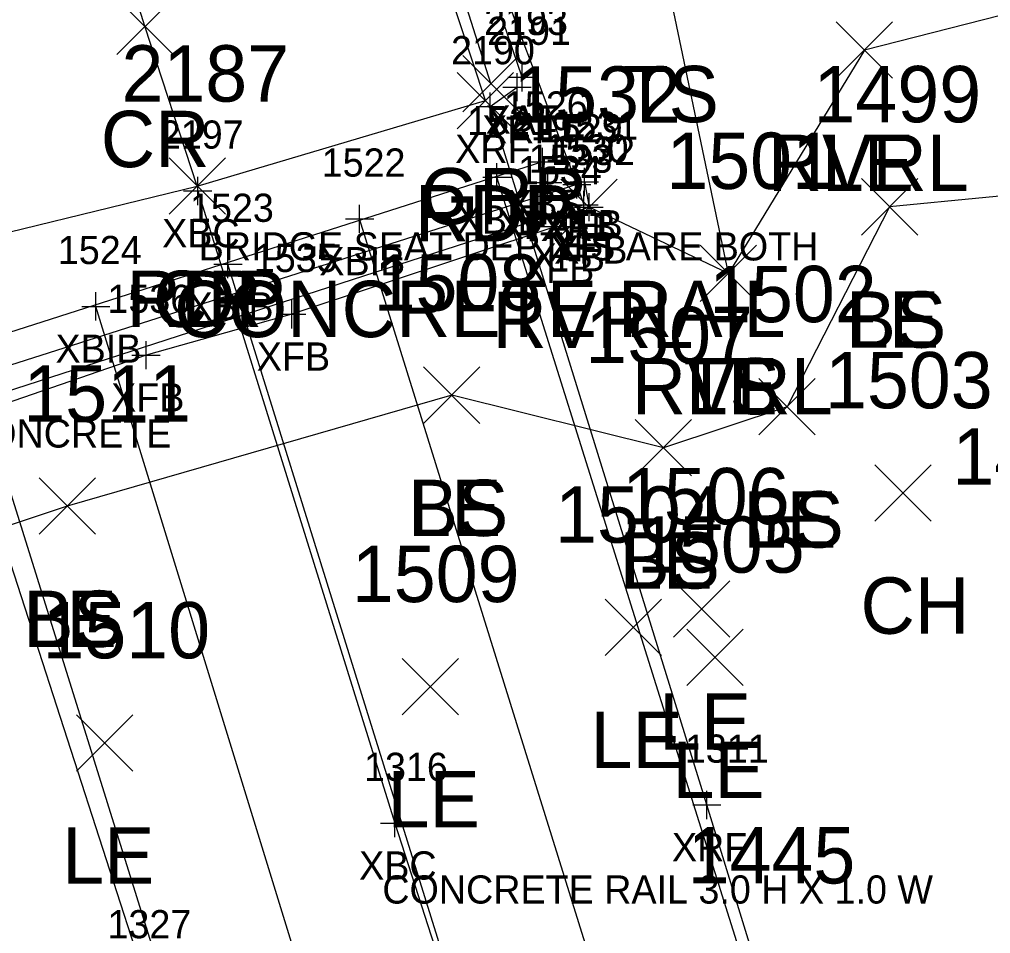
# Model space of a CAD drawing. Extents: x 1620157 to 1620595, y 115111 to 117885.
# Drawn here: x 1620323.63 to 1620358.1, y 115415.26 to 115447.7 of the extents above; entities that cross this region are included whole.
import ezdxf

# ---------------------------------------------------------------- set-up
doc = ezdxf.new("R2010")
doc.units = 0
for name, color, linetype in [('B_A', 7, 'Continuous'), ('B_C', 7, 'Continuous'), ('B_I', 7, 'Continuous'), ('B_TIC', 7, 'Continuous'), ('BB', 7, 'Continuous'), ('BELB', 7, 'Continuous'), ('BFT', 7, 'Continuous'), ('BR', 7, 'Continuous'), ('BSE', 7, 'Continuous'), ('BSUBM', 7, 'Continuous'), ('L_A', 7, 'Continuous'), ('L_I', 7, 'Continuous'), ('L_TIC', 7, 'Continuous'), ('LAWE', 7, 'Continuous'), ('LELB', 7, 'Continuous'), ('P_A', 7, 'Continuous'), ('P_I', 7, 'Continuous'), ('P_TIC', 7, 'Continuous'), ('PET', 7, 'Continuous'), ('PRC', 7, 'Continuous'), ('R_A', 7, 'Continuous'), ('R_C', 7, 'Continuous'), ('R_TIC', 7, 'Continuous'), ('RGR', 7, 'Continuous')]:
    doc.layers.add(name, color=color, linetype=linetype)

msp = doc.modelspace()

# ---------------------------------------------------------------- linework, layer by layer
at = {"layer": 'B_TIC'}
for p, q in [((1620341.474, 115445.647), (1620341.549, 115445.647)), ((1620341.297, 115445.297), (1620341.372, 115445.297)), ((1620340.342, 115444.608), (1620340.418, 115444.608)), ((1620342.201, 115442.646), (1620342.277, 115442.646)), ((1620340.583, 115442.1), (1620340.658, 115442.1)), ((1620342.383, 115441.912), (1620342.458, 115441.912)), ((1620343.419, 115441.84), (1620343.495, 115441.84)), ((1620343.419, 115441.84), (1620343.495, 115441.84)), ((1620343.686, 115441.931), (1620343.761, 115441.931)), ((1620329.963, 115441.614), (1620330.038, 115441.614)), ((1620343.669, 115441.12), (1620343.745, 115441.12)), ((1620343.854, 115441.035), (1620343.93, 115441.035)), ((1620343.054, 115440.758), (1620343.13, 115440.758)), ((1620335.708, 115440.621), (1620335.784, 115440.621)), ((1620342.677, 115440.348), (1620342.752, 115440.348)), ((1620331.035, 115439.016), (1620331.111, 115439.016)), ((1620326.343, 115437.517), (1620326.419, 115437.517)), ((1620333.3, 115437.236), (1620333.375, 115437.236)), ((1620328.129, 115435.785), (1620328.204, 115435.785)), ((1620348.034, 115419.821), (1620348.109, 115419.821)), ((1620348.034, 115419.821), (1620348.109, 115419.821)), ((1620336.954, 115419.174), (1620337.03, 115419.174))]:
    msp.add_line(p, q, dxfattribs=at)
for points in [[(1620341.47, 115445.147), (1620341.47, 115446.147)], [(1620341.294, 115444.797), (1620341.294, 115445.797)], [(1620340.97, 115445.647), (1620341.97, 115445.647)], [(1620340.339, 115444.108), (1620340.339, 115445.108)], [(1620340.793, 115445.297), (1620341.794, 115445.297)], [(1620339.839, 115444.608), (1620340.839, 115444.608)], [(1620342.198, 115442.146), (1620342.198, 115443.146)], [(1620340.579, 115441.6), (1620340.579, 115442.6)], [(1620341.698, 115442.646), (1620342.698, 115442.646)], [(1620342.38, 115441.412), (1620342.38, 115442.412)], [(1620343.682, 115441.431), (1620343.682, 115442.431)], [(1620329.959, 115441.114), (1620329.959, 115442.114)], [(1620340.079, 115442.1), (1620341.079, 115442.1)], [(1620343.416, 115441.34), (1620343.416, 115442.34)], [(1620343.416, 115441.34), (1620343.416, 115442.34)], [(1620341.88, 115441.912), (1620342.88, 115441.912)], [(1620342.916, 115441.84), (1620343.916, 115441.84)], [(1620342.916, 115441.84), (1620343.916, 115441.84)], [(1620343.182, 115441.931), (1620344.182, 115441.931)], [(1620329.459, 115441.614), (1620330.459, 115441.614)], [(1620343.666, 115440.62), (1620343.666, 115441.62)], [(1620343.851, 115440.535), (1620343.851, 115441.535)], [(1620335.705, 115440.121), (1620335.705, 115441.121)], [(1620343.051, 115440.258), (1620343.051, 115441.258)], [(1620343.166, 115441.12), (1620344.166, 115441.12)], [(1620343.351, 115441.035), (1620344.351, 115441.035)], [(1620342.551, 115440.758), (1620343.551, 115440.758)], [(1620342.673, 115439.848), (1620342.673, 115440.848)], [(1620335.205, 115440.621), (1620336.205, 115440.621)], [(1620342.173, 115440.348), (1620343.173, 115440.348)], [(1620331.032, 115438.516), (1620331.032, 115439.516)], [(1620330.532, 115439.016), (1620331.532, 115439.016)], [(1620326.34, 115437.017), (1620326.34, 115438.017)], [(1620333.296, 115436.736), (1620333.296, 115437.736)], [(1620325.84, 115437.517), (1620326.84, 115437.517)], [(1620332.796, 115437.236), (1620333.796, 115437.236)], [(1620328.125, 115435.285), (1620328.125, 115436.285)], [(1620327.625, 115435.785), (1620328.625, 115435.785)], [(1620348.03, 115419.321), (1620348.03, 115420.321)], [(1620348.03, 115419.321), (1620348.03, 115420.321)], [(1620336.951, 115418.674), (1620336.951, 115419.674)], [(1620347.53, 115419.821), (1620348.53, 115419.821)], [(1620347.53, 115419.821), (1620348.53, 115419.821)], [(1620336.451, 115419.174), (1620337.451, 115419.174)]]:
    msp.add_lwpolyline(points, dxfattribs=at)
at = {"layer": 'BB'}
for points in [[(1620354.301, 115398.372), (1620340.579, 115442.1)], [(1620349.354, 115396.802), (1620335.705, 115440.621)], [(1620344.626, 115395.358), (1620331.032, 115439.016)], [(1620339.807, 115393.755), (1620326.34, 115437.517)], [(1620335.374, 115392.294), (1620321.717, 115436.005)]]:
    msp.add_lwpolyline(points, dxfattribs=at)
at = {"layer": 'BELB'}
for points in [[(1620329.959, 115441.614), (1620336.951, 115419.174)], [(1620336.951, 115419.174), (1620345.538, 115392.547)]]:
    msp.add_lwpolyline(points, dxfattribs=at)
at = {"layer": 'BFT'}
for points in [[(1620343.416, 115441.84), (1620343.666, 115441.12), (1620317.302, 115432.591)], [(1620343.682, 115441.931), (1620343.851, 115441.035), (1620343.051, 115440.758), (1620342.673, 115440.348), (1620333.296, 115437.236), (1620328.125, 115435.785), (1620317.659, 115432.173)]]:
    msp.add_lwpolyline(points, dxfattribs=at)
at = {"layer": 'BR'}
for points in [[(1620348.03, 115419.821), (1620340.339, 115444.608), (1620341.294, 115445.297)], [(1620334.73, 115388.271), (1620335.779, 115388.568), (1620328.101, 115413.59), (1620319.786, 115439.283), (1620318.424, 115439.117), (1620318.652, 115437.704)], [(1620356.165, 115395.033), (1620355.736, 115394.792), (1620348.03, 115419.821)]]:
    msp.add_lwpolyline(points, dxfattribs=at)
at = {"layer": 'BSE'}
msp.add_lwpolyline([(1620342.198, 115442.646), (1620320.829, 115435.803)], dxfattribs=at)
at = {"layer": 'BSUBM'}
for points in [[(1620337.571, 115457.451), (1620339.875, 115451.242), (1620343.416, 115441.84), (1620319.154, 115434.099), (1620315.832, 115433.966), (1620311.124, 115433.881), (1620309.777, 115434.975)], [(1620341.47, 115445.647), (1620337.653, 115456.857)]]:
    msp.add_lwpolyline(points, dxfattribs=at)
at = {"layer": 'L_TIC'}
for points in [[(1620352.621, 115445.61), (1620354.621, 115447.61)], [(1620354.621, 115445.61), (1620352.621, 115447.61)], [(1620352.621, 115445.61), (1620354.621, 115447.61)], [(1620354.621, 115445.61), (1620352.621, 115447.61)], [(1620342.851, 115440.035), (1620344.851, 115442.035)], [(1620344.851, 115440.035), (1620342.851, 115442.035)], [(1620353.516, 115440.049), (1620355.516, 115442.049)], [(1620355.516, 115440.049), (1620353.516, 115442.049)], [(1620353.516, 115440.049), (1620355.516, 115442.049)], [(1620355.516, 115440.049), (1620353.516, 115442.049)], [(1620347.794, 115437.684), (1620349.794, 115439.684)], [(1620349.794, 115437.684), (1620347.794, 115439.684)], [(1620347.794, 115437.684), (1620349.794, 115439.684)], [(1620349.794, 115437.684), (1620347.794, 115439.684)], [(1620347.794, 115437.684), (1620349.794, 115439.684)], [(1620349.794, 115437.684), (1620347.794, 115439.684)], [(1620337.973, 115433.365), (1620339.973, 115435.365)], [(1620339.973, 115433.365), (1620337.973, 115435.365)], [(1620337.973, 115433.365), (1620339.973, 115435.365)], [(1620339.973, 115433.365), (1620337.973, 115435.365)], [(1620349.878, 115432.955), (1620351.878, 115434.955)], [(1620351.878, 115432.955), (1620349.878, 115434.955)], [(1620349.878, 115432.955), (1620351.878, 115434.955)], [(1620351.878, 115432.955), (1620349.878, 115434.955)], [(1620345.485, 115431.501), (1620347.485, 115433.501)], [(1620347.485, 115431.501), (1620345.485, 115433.501)], [(1620345.485, 115431.501), (1620347.485, 115433.501)], [(1620347.485, 115431.501), (1620345.485, 115433.501)], [(1620353.994, 115429.897), (1620355.994, 115431.897)], [(1620355.994, 115429.897), (1620353.994, 115431.897)], [(1620324.326, 115429.427), (1620326.326, 115431.427)], [(1620326.326, 115429.427), (1620324.326, 115431.427)], [(1620324.326, 115429.427), (1620326.326, 115431.427)], [(1620326.326, 115429.427), (1620324.326, 115431.427)], [(1620346.842, 115425.781), (1620348.842, 115427.781)], [(1620348.842, 115425.781), (1620346.842, 115427.781)], [(1620344.414, 115425.129), (1620346.414, 115427.129)], [(1620346.414, 115425.129), (1620344.414, 115427.129)], [(1620347.32, 115424.064), (1620349.32, 115426.064)], [(1620349.32, 115424.064), (1620347.32, 115426.064)], [(1620337.21, 115423.021), (1620339.21, 115425.021)], [(1620339.21, 115423.021), (1620337.21, 115425.021)], [(1620325.659, 115421.024), (1620327.659, 115423.024)], [(1620327.659, 115421.024), (1620325.659, 115423.024)]]:
    msp.add_lwpolyline(points, dxfattribs=at)
at = {"layer": 'LAWE'}
msp.add_lwpolyline([(1620445.954, 115439.559), (1620430.826, 115447.795), (1620415.576, 115450.852), (1620397.572, 115447.406), (1620383.813, 115449.588), (1620366.252, 115449.835), (1620353.621, 115446.61), (1620348.794, 115438.684), (1620343.851, 115441.035)], dxfattribs=at)
at = {"layer": 'LELB'}
for points in [[(1620348.794, 115438.684), (1620346.629, 115449.051)], [(1620445.933, 115434.696), (1620432.19, 115440.311), (1620415.154, 115443.989), (1620397.761, 115444.055), (1620388.34, 115442.493), (1620368.19, 115442.372), (1620354.516, 115441.049), (1620350.878, 115433.955), (1620346.485, 115432.501), (1620338.973, 115434.365), (1620325.326, 115430.427), (1620316.032, 115427.322), (1620308.723, 115416.914), (1620294.485, 115412.65), (1620281.316, 115408.44), (1620263.956, 115399.244), (1620237.914, 115391.699), (1620225.014, 115391.235), (1620212.858, 115385.97)]]:
    msp.add_lwpolyline(points, dxfattribs=at)
at = {"layer": 'P_TIC'}
for points in [[(1620327.083, 115446.457), (1620329.083, 115448.457)], [(1620329.083, 115446.457), (1620327.083, 115448.457)], [(1620339.172, 115443.819), (1620341.172, 115445.819)], [(1620341.172, 115443.819), (1620339.172, 115445.819)], [(1620328.944, 115440.783), (1620330.944, 115442.783)], [(1620330.944, 115440.783), (1620328.944, 115442.783)], [(1620328.944, 115440.783), (1620330.944, 115442.783)], [(1620330.944, 115440.783), (1620328.944, 115442.783)]]:
    msp.add_lwpolyline(points, dxfattribs=at)
at = {"layer": 'PET'}
for points in [[(1620340.172, 115444.819), (1620336.223, 115456.795)], [(1620320.138, 115439.395), (1620329.944, 115441.783), (1620340.172, 115444.819)]]:
    msp.add_lwpolyline(points, dxfattribs=at)
at = {"layer": 'PRC'}
for points in [[(1620328.083, 115447.457), (1620322.143, 115466.609), (1620311.316, 115499.812), (1620303.781, 115522.909), (1620294.725, 115551.741), (1620279.311, 115600.233), (1620271.119, 115626.45), (1620257.914, 115669.486), (1620247.637, 115703.034), (1620242.452, 115719.653), (1620232.976, 115752.347), (1620223.662, 115784.044), (1620214.136, 115816.154), (1620207.469, 115841.181)], [(1620329.944, 115441.783), (1620328.083, 115447.457)]]:
    msp.add_lwpolyline(points, dxfattribs=at)
at = {"layer": 'R_TIC'}
for points in [[(1620339.366, 115444.424), (1620341.366, 115446.424)], [(1620341.366, 115444.424), (1620339.366, 115446.424)]]:
    msp.add_lwpolyline(points, dxfattribs=at)
at = {"layer": 'RGR'}
msp.add_lwpolyline([(1620340.366, 115445.424), (1620336.824, 115456.591)], dxfattribs=at)

# ---------------------------------------------------------------- texts
at = {"layer": 'B_A'}
for s, p in [('XAT', (1620340.175, 115443.647)), ('XRF', (1620340.053, 115443.297)), ('XRF', (1620339.098, 115442.608)), ('XBS', (1620340.938, 115440.646)), ('XBIB', (1620339.15, 115440.1)), ('XBC', (1620328.696, 115439.614)), ('XFAT', (1620340.635, 115439.912)), ('XAB', (1620342.136, 115439.84)), ('XFT', (1620342.16, 115439.84)), ('XFB', (1620342.442, 115439.931)), ('XFT', (1620342.41, 115439.12)), ('XFB', (1620342.611, 115439.035)), ('XBIB', (1620334.276, 115438.621)), ('XFB', (1620341.811, 115438.758)), ('XFB', (1620341.433, 115438.348)), ('XBIB', (1620329.603, 115437.016)), ('XBIB', (1620324.911, 115435.517)), ('XFB', (1620332.056, 115435.236)), ('XFB', (1620326.885, 115433.785)), ('XRF', (1620346.79, 115417.821)), ('XRF', (1620346.79, 115417.821)), ('XBC', (1620335.687, 115417.174))]:
    msp.add_text(s, height=1, dxfattribs=at).set_placement(p)
at = {"layer": 'B_C'}
for s, p in [('BRIDGE SEAT DEPTHS ARE BOTH', (1620329.994, 115439.146)), ('BEAMS ARE CONCRETE', (1620313.347, 115432.505)), ('CONCRETE RAIL 3.0 H X 1.0 W', (1620336.511, 115416.321)), ('CONCRETE RAIL 3.0 H X 1.0 W', (1620336.511, 115416.321))]:
    msp.add_text(s, height=1, dxfattribs=at).set_placement(p)
at = {"layer": 'B_I'}
for s, p in [('2193', (1620340.124, 115447.147)), ('2191', (1620340.231, 115446.797)), ('2190', (1620338.949, 115446.108)), ('1526', (1620340.824, 115444.146)), ('1521', (1620339.516, 115443.6)), ('2192', (1620341.033, 115443.412)), ('1531', (1620342.619, 115443.431)), ('2197', (1620328.613, 115443.114)), ('1529', (1620342.066, 115443.34)), ('1529', (1620342.066, 115443.34)), ('1530', (1620342.276, 115442.62)), ('1532', (1620342.505, 115442.535)), ('1522', (1620334.358, 115442.121)), ('1533', (1620341.704, 115442.258)), ('1534', (1620341.327, 115441.848)), ('1523', (1620329.685, 115440.516)), ('1524', (1620324.994, 115439.017)), ('1535', (1620331.95, 115438.736)), ('1536', (1620326.752, 115437.285)), ('1311', (1620347.251, 115421.321)), ('1311', (1620347.251, 115421.321)), ('1316', (1620335.861, 115420.674)), ('1327', (1620326.755, 115415.09))]:
    msp.add_text(s, height=1, dxfattribs=at).set_placement(p)
at = {"layer": 'L_A'}
for s, p in [('TS', (1620345.038, 115444.051)), ('RVRL', (1620350.188, 115441.61)), ('LE', (1620352.109, 115441.61)), ('RVRL', (1620340.418, 115436.035)), ('BS', (1620352.957, 115436.049)), ('LE', (1620353.004, 115436.049)), ('RVRL', (1620345.361, 115433.684)), ('TS', (1620347.204, 115433.684)), ('LE', (1620347.283, 115433.684)), ('BS', (1620337.414, 115429.365)), ('LE', (1620337.462, 115429.365)), ('BS', (1620349.319, 115428.955)), ('LE', (1620349.367, 115428.955)), ('BS', (1620344.926, 115427.501)), ('LE', (1620344.973, 115427.501)), ('CH', (1620353.482, 115425.897)), ('BS', (1620323.767, 115425.427)), ('LE', (1620323.814, 115425.427)), ('LE', (1620346.331, 115421.781)), ('LE', (1620343.902, 115421.129)), ('LE', (1620346.808, 115420.064)), ('LE', (1620336.698, 115419.021)), ('LE', (1620325.148, 115417.024))]:
    msp.add_text(s, height=2, dxfattribs=at).set_placement(p)
at = {"layer": 'L_I'}
for s, p in [('1532', (1620341.158, 115444.035)), ('1499', (1620351.815, 115444.049)), ('1499', (1620351.815, 115444.049)), ('1501', (1620346.59, 115441.684)), ('1501', (1620346.59, 115441.684)), ('1501', (1620346.59, 115441.684)), ('1508', (1620336.202, 115437.365)), ('1508', (1620336.202, 115437.365)), ('1502', (1620348.107, 115436.955)), ('1502', (1620348.107, 115436.955)), ('1507', (1620343.713, 115435.501)), ('1507', (1620343.713, 115435.501)), ('1503', (1620352.223, 115433.897)), ('1511', (1620323.767, 115433.427)), ('1511', (1620323.767, 115433.427)), ('1498', (1620356.743, 115431.189)), ('1506', (1620345.016, 115429.781)), ('1504', (1620342.642, 115429.129)), ('1505', (1620345.549, 115428.064)), ('1509', (1620335.43, 115427.021)), ('1510', (1620324.447, 115425.024)), ('1445', (1620347.347, 115417.034))]:
    msp.add_text(s, height=2, dxfattribs=at).set_placement(p)
at = {"layer": 'P_A'}
for s, p in [('CR', (1620326.516, 115442.457)), ('RDP', (1620337.661, 115439.819)), ('RDP', (1620327.433, 115436.783)), ('CR', (1620328.377, 115436.783))]:
    msp.add_text(s, height=2, dxfattribs=at).set_placement(p)
at = {"layer": 'P_I'}
msp.add_text('2187', height=2, dxfattribs=at).set_placement((1620327.252, 115444.783))
msp.add_text('2187', height=2, dxfattribs=at).set_placement((1620327.252, 115444.783))
at = {"layer": 'R_A'}
msp.add_text('GRR', height=2, dxfattribs=at).set_placement((1620337.854, 115440.424))
at = {"layer": 'R_C'}
msp.add_text('CONCRETE RAIL', height=2, dxfattribs=at).set_placement((1620329.122, 115436.424))

doc.saveas('drawing.dxf')
